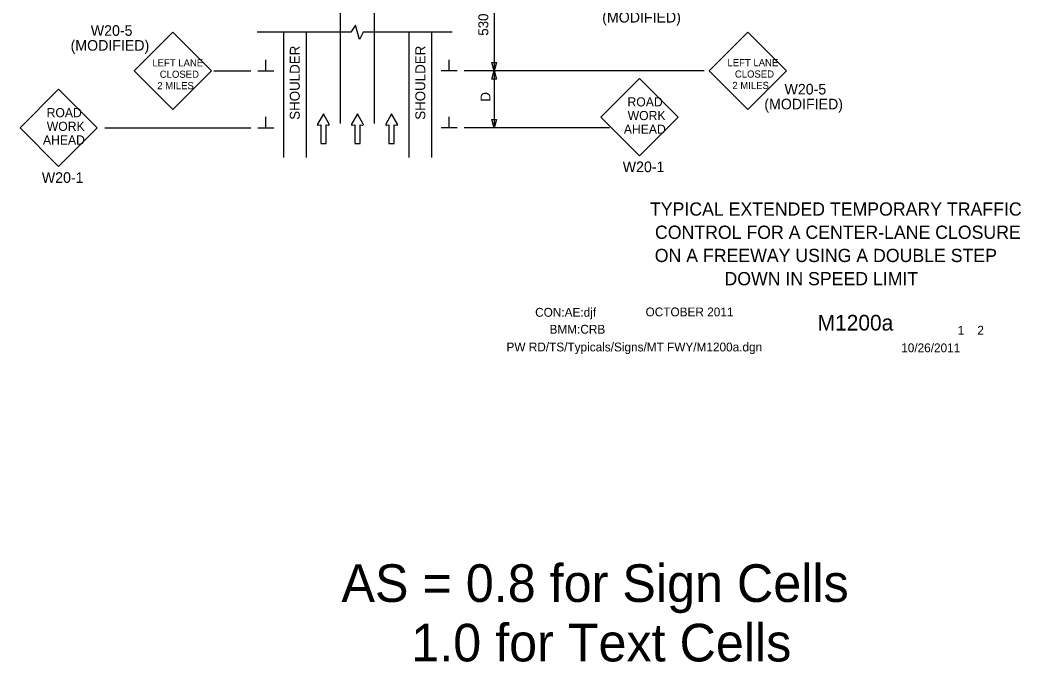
# Model space of a CAD drawing. Extents: x 16729 to 18482, y 7002 to 8333.
# Drawn here: x 16729 to 17432, y 7002 to 7453 of the extents above; entities that cross this region are included whole.
import ezdxf

# ---------------------------------------------------------------- set-up
doc = ezdxf.new("R2010")
doc.units = 0
for name, color, linetype in [('ALI_LEGAL_EX', 7, 'Continuous'), ('BORDER', 7, 'Continuous'), ('BORDER_SIGNAL_WO', 7, 'Continuous'), ('MT_SCRATCH_LEVEL_E', 7, 'Continuous'), ('PAVT_EDGE_EX', 7, 'Continuous'), ('TRAFFIC_SIGNS_PR', 7, 'Continuous'), ('TYPICAL_TEXT_DIMEN_PR', 7, 'Continuous')]:
    doc.layers.add(name, color=color, linetype=linetype)

msp = doc.modelspace()

# ---------------------------------------------------------------- linework, layer by layer
at = {"layer": 'ALI_LEGAL_EX'}
for p, q in [((16953.87, 7379.99), (16953.87, 7560.8)), ((16977.87, 7379.99), (16977.87, 7560.8))]:
    msp.add_line(p, q, dxfattribs=at)
for points in [[(16953.87, 7380.93), (16953.87, 7405.93)], [(16977.87, 7380.93), (16977.87, 7405.93)]]:
    msp.add_lwpolyline(points, dxfattribs=at)
at = {"layer": 'MT_SCRATCH_LEVEL_E'}
for p, q in [((16941.87, 7386.81), (16937.75, 7379.57)), ((16946.01, 7379.57), (16941.87, 7386.81)), ((16965.77, 7386.81), (16961.66, 7379.57)), ((16969.92, 7379.57), (16965.77, 7386.81)), ((16989.82, 7386.81), (16985.71, 7379.57)), ((16993.97, 7379.57), (16989.82, 7386.81)), ((16938.24, 7378.88), (16940.01, 7379.2)), ((16940.01, 7379.2), (16940.01, 7365.94)), ((16943.76, 7365.94), (16943.76, 7379.2)), ((16943.76, 7379.2), (16945.53, 7378.88)), ((16962.14, 7378.88), (16963.92, 7379.2)), ((16963.92, 7379.2), (16963.92, 7365.94)), ((16967.66, 7365.94), (16967.66, 7379.2)), ((16967.66, 7379.2), (16969.44, 7378.88)), ((16986.19, 7378.88), (16987.97, 7379.2)), ((16987.97, 7379.2), (16987.97, 7365.94)), ((16991.71, 7365.94), (16991.71, 7379.2)), ((16991.71, 7379.2), (16993.49, 7378.88)), ((16940.01, 7365.94), (16943.76, 7365.94)), ((16963.92, 7365.94), (16967.66, 7365.94)), ((16987.97, 7365.94), (16991.71, 7365.94))]:
    msp.add_line(p, q, dxfattribs=at)
for centre, start, end in [((16938.16, 7379.34), 150.42484, 279.96381), ((16945.6, 7379.34), 260.03619, 29.77312), ((16962.07, 7379.34), 150.42484, 279.96381), ((16969.51, 7379.34), 260.03619, 29.77312), ((16986.12, 7379.34), 150.42484, 279.96381), ((16993.56, 7379.34), 260.03619, 29.77312)]:
    msp.add_arc(centre, 0.463, start, end, dxfattribs=at)
at = {"layer": 'PAVT_EDGE_EX'}
for p, q in [((16913.87, 7444.25), (16913.87, 7356.17)), ((16929.87, 7444.25), (16929.87, 7356.17)), ((17001.87, 7444.25), (17001.87, 7356.17)), ((17017.87, 7444.25), (17017.87, 7356.17))]:
    msp.add_line(p, q, dxfattribs=at)
at = {"layer": 'TRAFFIC_SIGNS_PR'}
for p, q in [((16836.1, 7444.12), (16808.95, 7416.97)), ((16863.25, 7416.97), (16836.1, 7444.12)), ((17240.23, 7444.28), (17213.08, 7417.12)), ((17267.38, 7417.12), (17240.23, 7444.28)), ((16808.95, 7416.97), (16836.1, 7389.82)), ((16836.1, 7389.82), (16863.25, 7416.97)), ((17213.08, 7417.12), (17240.23, 7389.97)), ((17240.23, 7389.97), (17267.38, 7417.12)), ((17164.05, 7411.64), (17136.9, 7384.48)), ((17191.21, 7384.48), (17164.05, 7411.64)), ((16755.86, 7404.08), (16728.71, 7376.93)), ((16783.01, 7376.93), (16755.86, 7404.08)), ((17136.9, 7384.48), (17164.05, 7357.33)), ((17164.05, 7357.33), (17191.21, 7384.48)), ((16728.71, 7376.93), (16755.86, 7349.78)), ((16755.86, 7349.78), (16783.01, 7376.93))]:
    msp.add_line(p, q, dxfattribs=at)
at = {"layer": 'TYPICAL_TEXT_DIMEN_PR'}
for p, q in [((17061.87, 7498.5), (17061.87, 7416.94)), ((16964.47, 7449.05), (16961.21, 7444.25)), ((16967.21, 7439.11), (16964.47, 7449.05)), ((16961.21, 7444.25), (16895.27, 7444.25)), ((16969.95, 7444.25), (16967.21, 7439.11)), ((17032.29, 7444.25), (16969.95, 7444.25)), ((16901.49, 7416.94), (16901.49, 7424.72)), ((17030.24, 7416.94), (17030.24, 7424.72)), ((17061.87, 7416.94), (17060.3, 7422.8)), ((17060.3, 7422.8), (17061.87, 7422.8)), ((17061.87, 7422.8), (17063.44, 7422.8)), ((17063.44, 7422.8), (17061.87, 7416.94)), ((16864.96, 7416.94), (16890.87, 7416.94)), ((16895.87, 7416.94), (16907.12, 7416.94)), ((17035.87, 7416.94), (17024.62, 7416.94)), ((17209.56, 7416.94), (17040.87, 7416.94)), ((17060.3, 7411.07), (17061.87, 7416.94)), ((17061.87, 7416.94), (17061.87, 7376.94)), ((17061.87, 7416.94), (17063.44, 7411.07)), ((17061.87, 7411.07), (17060.3, 7411.07)), ((17063.44, 7411.07), (17061.87, 7411.07)), ((16901.49, 7376.94), (16901.49, 7384.72)), ((17030.24, 7376.94), (17030.24, 7384.72)), ((17061.87, 7376.94), (17060.3, 7382.8)), ((17060.3, 7382.8), (17061.87, 7382.8)), ((17061.87, 7382.8), (17063.44, 7382.8)), ((17063.44, 7382.8), (17061.87, 7376.94)), ((16788.3, 7376.94), (16890.87, 7376.94)), ((16895.87, 7376.94), (16907.12, 7376.94)), ((17035.87, 7376.94), (17024.62, 7376.94)), ((17142.83, 7376.94), (17040.87, 7376.94))]:
    msp.add_line(p, q, dxfattribs=at)

# ---------------------------------------------------------------- texts
at = {"layer": 'BORDER'}
for s, p in [('TYPICAL EXTENDED TEMPORARY TRAFFIC', (17171.38, 7315.31)), ('CONTROL FOR A CENTER-LANE CLOSURE', (17174.9, 7299.01)), ('ON A FREEWAY USING A DOUBLE STEP ', (17174.75, 7282.71)), ('DOWN IN SPEED LIMIT', (17223.75, 7266.41))]:
    msp.add_text(s, height=9.3, dxfattribs=at).set_placement(p)
at = {"layer": 'BORDER_SIGNAL_WO'}
for s, height, p in [('CON:AE:djf  ', 6.2, (17090.69, 7244.31)), ('    OCTOBER 2011    ', 6.2, (17159.08, 7244.59)), ('    M1200a   ', 11, (17272.86, 7234.63)), ('BMM:CRB   ', 6.2, (17100.81, 7232.42)), (' 1    2 ', 6.2, (17385.3, 7231.72)), ('PW RD/TS/Typicals/Signs/MT FWY/M1200a.dgn      ', 6.2, (17070.55, 7219.96)), ('10/26/2011    ', 6.2, (17347.93, 7219.38)), ('AS = 0.8 for Sign Cells', 26.4241, (16954.57, 7044.01)), ('     1.0 for Text Cells', 26.4241, (16954.57, 7002.22))]:
    msp.add_text(s, height=height, dxfattribs=at).set_placement(p)
at = {"layer": 'TRAFFIC_SIGNS_PR'}
for s, height, p in [('(MODIFIED)', 7.44, (17137.85, 7450.95)), ('W20-5', 7.44, (16778.44, 7441.61)), ('(MODIFIED)', 7.44, (16764.26, 7431.17)), ('LEFT LANE', 5, (16821.73, 7420.13)), ('LEFT LANE', 5, (17225.86, 7420.28)), ('CLOSED', 5, (16826.94, 7412.13)), ('CLOSED', 5, (17231.07, 7412.28)), ('2 MILES', 5, (16825.19, 7404.13)), ('2 MILES', 5, (17229.32, 7404.28)), ('W20-5', 7.44, (17265.93, 7400.4)), ('ROAD', 6.4, (17155.59, 7392.02)), ('(MODIFIED)', 7.44, (17251.75, 7389.96)), ('ROAD', 6.4, (16747.4, 7384.47)), ('WORK', 6.4, (17155.7, 7382.42)), ('WORK', 6.4, (16747.51, 7374.87)), ('AHEAD', 6.4, (17153.01, 7372.82)), ('AHEAD', 6.4, (16744.82, 7365.27)), ('W20-1', 7.44, (17152.22, 7345.89)), ('W20-1', 7.44, (16744.03, 7338.34))]:
    msp.add_text(s, height=height, dxfattribs=at).set_placement(p)
at = {"layer": 'TYPICAL_TEXT_DIMEN_PR'}
for s, p in [('5300 ft', (17057.78, 7441.66)), ('SHOULDER', (16925.29, 7382.65)), ('SHOULDER', (17013.49, 7382.65)), ('D', (17059.31, 7395.36))]:
    msp.add_text(s, height=7, rotation=90, dxfattribs=at).set_placement(p)

doc.saveas('drawing.dxf')
